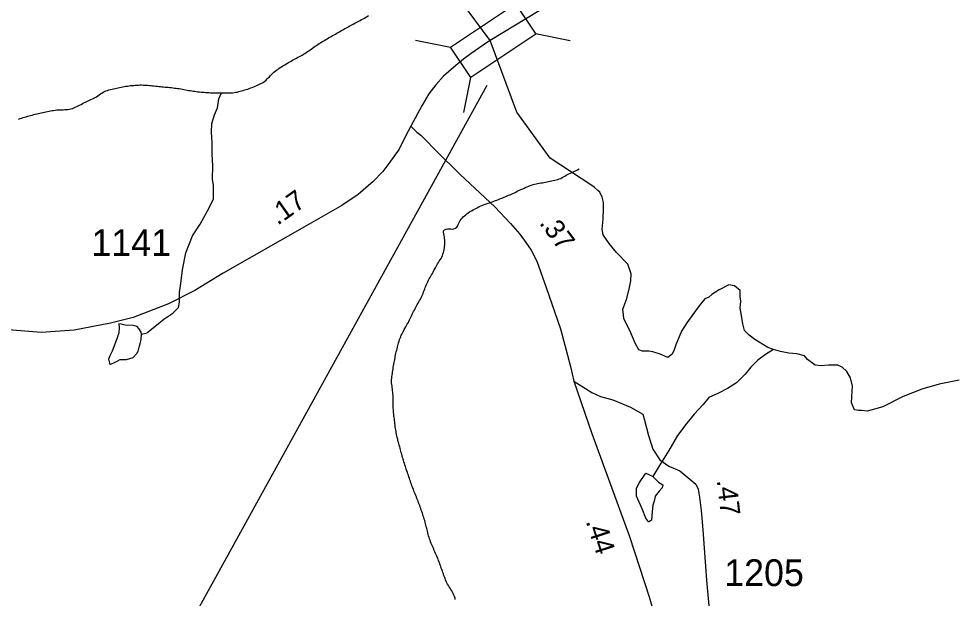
# Model space of a CAD drawing. Extents: x 1950930 to 2061844, y 904556 to 1017002.
# Drawn here: x 1996439 to 2002388, y 935305 to 938988 of the extents above; entities that cross this region are included whole.
import ezdxf

# ---------------------------------------------------------------- set-up
doc = ezdxf.new("R2010")
doc.units = 0
for name, color, linetype in [('Exist Hydrographic Creek Single Shore', 7, 'Continuous'), ('Exist Hydrographic Misc Water Feature', 7, 'Continuous'), ('Exist Road Primary US Structure Standard Bridge CELL', 7, 'Continuous'), ('Exist Road Secondary Structure Standard Bridge CELL', 7, 'Continuous'), ('Exist Road Secondary Structure Standard Bridge Number Label', 7, 'Continuous'), ('Exist Road Secondary Type 51 Attributed', 7, 'Continuous'), ('Exist Road Secondary Type 51 Number Label', 7, 'Continuous')]:
    doc.layers.add(name, color=color, linetype=linetype)

msp = doc.modelspace()

# ---------------------------------------------------------------- linework, layer by layer
at = {"layer": 'Exist Hydrographic Creek Single Shore'}
for points in [[(2000079.1, 937928.9), (1999814, 938102), (1999602, 938394.6), (1999434.4, 938849.1), (1999244, 939104.3), (1999193.9, 939144.7)], [(1997726.7, 938516.3), (1997736.5, 938516.9), (1997747, 938517.3), (1997756.6, 938517.4), (1997766.9, 938517.1), (1997777.1, 938517.6), (1997787, 938518.2), (1997796.8, 938518.3), (1997806.9, 938519.6), (1997816.7, 938520.9), (1997826.3, 938522.4), (1997836.2, 938524.9), (1997845.4, 938527.5), (1997855.3, 938530), (1997865.1, 938533), (1997874.7, 938535.3), (1997884.4, 938538.7), (1997894.2, 938541.6), (1997903.6, 938544.7), (1997913.1, 938548.5), (1997922.5, 938551.5), (1997932.2, 938555.4), (1997941.2, 938559.3), (1997950.8, 938563.5), (1997959.6, 938567.4), (1997968.9, 938571.3), (1997977.7, 938576), (1997986.5, 938580.8), (1997994.5, 938585.2), (1998002.3, 938591.8), (1998009.9, 938598.3), (1998017.5, 938605.3), (1998024.2, 938612.8), (1998031.2, 938619.9), (1998038, 938627.3), (1998044.7, 938634.4), (1998052.3, 938641.8), (1998059.7, 938648), (1998067.7, 938654.5), (1998075.5, 938661), (1998084.1, 938666.2), (1998091.7, 938671.9), (1998100.3, 938677.5), (1998108.5, 938683.1), (1998117.1, 938688.8), (1998125.5, 938693.6), (1998134.5, 938699.1), (1998142.5, 938703.5), (1998151.6, 938709.1), (1998160, 938714.3), (1998168.6, 938719.5), (1998177.4, 938724.2), (1998185.8, 938729.1), (1998195.2, 938733.7), (1998203.6, 938738.5), (1998212.5, 938743.3), (1998221.3, 938748), (1998230.1, 938752.7), (1998239.1, 938757.5), (1998247.5, 938763.1), (1998256.1, 938767.9), (1998264.7, 938773.4), (1998272.7, 938779.1), (1998280.9, 938784.4), (1998289.6, 938790), (1998297.3, 938795.7), (1998305.8, 938801.3), (1998314, 938807), (1998322.4, 938813.4), (1998330.4, 938818.7), (1998338.6, 938824.3), (1998347.2, 938829.9), (1998355.4, 938835.6), (1998363.8, 938840.4), (1998372.4, 938846), (1998380.8, 938850.8), (1998389.8, 938856.3), (1998398.2, 938860.7), (1998406.6, 938865.9), (1998415.3, 938871.2), (1998424.1, 938875.9), (1998432.9, 938880.6), (1998441.5, 938886.2), (1998449.9, 938891), (1998458.7, 938895.8), (1998467.7, 938900.5), (1998476.6, 938905.2), (1998485.2, 938910.8), (1998494, 938915.5), (1998502.4, 938920.4), (1998511.2, 938925.1), (1998520.2, 938929.9), (1998529.1, 938934.6), (1998537.7, 938940.2), (1998546.5, 938945), (1998554.9, 938949.7), (1998563.7, 938954.5), (1998572.7, 938959.2), (1998581.6, 938963.9), (1998590.4, 938968.7)], [(1996816.5, 938434.3), (1996825.7, 938439), (1996834.7, 938443.7), (1996843.5, 938448.5), (1996852.8, 938453.2), (1996862, 938457.1), (1996870.8, 938461.8), (1996879.4, 938465.8), (1996888.6, 938469.7), (1996897.9, 938474.3), (1996907.1, 938478.2), (1996915.9, 938482.9), (1996924.7, 938487.7), (1996933.8, 938492.4), (1996941.7, 938498.1), (1996950.6, 938504.4), (1996958.4, 938510.2), (1996967, 938515.8), (1996975.4, 938520.9), (1996983.8, 938525.7), (1996993, 938529.6), (1997002, 938532.7), (1997011.9, 938535.4), (1997021.7, 938538.3), (1997031.4, 938540.5), (1997040.6, 938542.8), (1997050.8, 938544.8), (1997060.5, 938547.4), (1997070.3, 938549.5), (1997080, 938551.8), (1997090, 938553.8), (1997099.6, 938555.7), (1997109.7, 938557), (1997119.9, 938559.1), (1997129.8, 938560.4), (1997139.8, 938562.1), (1997149.3, 938562.8), (1997159.7, 938564), (1997169.6, 938564.5), (1997179.2, 938566.2), (1997189.5, 938566.8), (1997199.3, 938566.4), (1997209.1, 938567.1), (1997219.4, 938567.1), (1997229, 938566.9), (1997239.3, 938566.5), (1997249.3, 938565.4), (1997259, 938565.1), (1997269, 938564.4), (1997279.5, 938563.3), (1997289.5, 938562.1), (1997299.2, 938561), (1997309.2, 938560.3), (1997319.3, 938559.3), (1997329.1, 938558.1), (1997339.1, 938557), (1997348.8, 938556), (1997358.8, 938555.3), (1997368.9, 938554.1), (1997379.1, 938553.7), (1997389, 938552.7), (1997399.2, 938552), (1997408.7, 938550.9), (1997419.1, 938548.9), (1997428.5, 938547.9), (1997438.6, 938546.8), (1997448.4, 938544.8), (1997458.5, 938544.1), (1997468.5, 938542.3), (1997478.4, 938540.3), (1997487.8, 938538.5), (1997497.6, 938536.5), (1997507.9, 938534.6), (1997517.5, 938532.7), (1997527.4, 938531.2), (1997537.4, 938530.2), (1997546.9, 938528.3), (1997557.3, 938527.1), (1997566.7, 938525.2), (1997576.8, 938524.5), (1997586.8, 938523.4), (1997596.9, 938522.3), (1997606.5, 938522.1), (1997616.6, 938520.9), (1997626.6, 938520.2), (1997636.9, 938519.9), (1997646.9, 938518.8), (1997656.4, 938517.7), (1997666.6, 938517.3), (1997676.9, 938517.4), (1997686.5, 938517.2), (1997696.8, 938516.8), (1997706.4, 938516.6), (1997726.7, 938516.3)], [(1996437.9, 938350.2), (1996447.4, 938354), (1996456.8, 938357.1), (1996466.6, 938360.1), (1996476.5, 938362.2), (1996485.9, 938365.7), (1996495.4, 938368.7), (1996505, 938370.8), (1996514.4, 938373.9), (1996524.3, 938376.1), (1996534.1, 938379), (1996543.7, 938381.6), (1996553.6, 938383.8), (1996563.2, 938386), (1996572.9, 938388.2), (1996582.3, 938390.8), (1996592.3, 938392.9), (1996602.2, 938395.1), (1996611.8, 938397.3), (1996621.9, 938398.9), (1996631.7, 938401.2), (1996641.3, 938403.3), (1996651.4, 938404.7), (1996660.8, 938406), (1996670.9, 938407.7), (1996681.3, 938408.2), (1996691.2, 938408.8), (1996701, 938409.7), (1996711.3, 938409.4), (1996721.5, 938409.8), (1996731.8, 938410.3), (1996741.2, 938411.2), (1996751.1, 938411.8), (1996761.1, 938413.2), (1996770.3, 938415.3), (1996779.8, 938418.4), (1996789.2, 938421.5), (1996798.4, 938425.7), (1996807.9, 938430.4), (1996816.5, 938434.3)], [(2001233.7, 936885.8), (2001197.8, 936897.7), (2001113.6, 936949.6), (2001077.7, 936977.6), (2001049.8, 937005.7), (2001037.5, 937049.6), (2001029.4, 937101.6), (2001021.6, 937149.7), (2001025.4, 937193.6), (2001021.4, 937221.6), (2001021.6, 937261.6), (2000985.4, 937289.6), (2000949.5, 937297.6), (2000887.4, 937265.4), (2000841.5, 937235.5), (2000821.5, 937219.5), (2000797.6, 937207.5), (2000761.6, 937163.3), (2000721.4, 937107.4), (2000681.6, 937055.3), (2000649.7, 937003.5), (2000613.7, 936915.3), (2000601.6, 936883.4), (2000589.8, 936855.4), (2000561.9, 936835.3), (2000513.7, 936855.3), (2000465.8, 936871.1), (2000441.6, 936875.2), (2000401.6, 936875.4), (2000377.8, 936883.1), (2000353.7, 936927.2), (2000319.6, 937007), (2000295.7, 937055.1), (2000283.4, 937083.3), (2000279.7, 937107.3), (2000275.5, 937143.2), (2000299.4, 937203.1), (2000315.5, 937269.3), (2000327.5, 937323.2), (2000329.3, 937367.2), (2000307.3, 937427.4), (2000235.3, 937503), (2000189.3, 937559.1), (2000151.4, 937615), (2000145.2, 937651.2), (2000151.1, 937715.1), (2000153.1, 937781), (2000153, 937821.1), (2000145.1, 937853.1), (2000129, 937885.2), (2000117.1, 937897), (2000093, 937917.2), (2000079.1, 937928.9)], [(2002412, 936690.4), (2002285.8, 936666.4), (2002175.9, 936634.3), (2002055.8, 936586.2), (2001928.1, 936522.2), (2001874, 936506.3), (2001828.1, 936494.1), (2001792.1, 936498.1), (2001772.1, 936498.2), (2001747.9, 936502), (2001728.1, 936546), (2001729.9, 936586), (2001733.9, 936653.9), (2001721.9, 936706), (2001697.8, 936745.9), (2001669.8, 936774), (2001641.8, 936786.1), (2001581.8, 936786), (2001533.8, 936782.1), (2001497.7, 936785.8), (2001449.6, 936821.9), (2001429.8, 936845.9), (2001381.8, 936857.8), (2001329.7, 936861.8), (2001277.7, 936873.7), (2001233.7, 936885.8)]]:
    msp.add_lwpolyline(points, dxfattribs=at)
at = {"layer": 'Exist Hydrographic Misc Water Feature'}
for points in [[(1998590.4, 938968.7), (1998598.8, 938973.1), (1998607.6, 938977.9), (1998616.6, 938983), (1998625.8, 938987.6), (1998634.5, 938991.2), (1998643.1, 938997.2), (1998651.5, 939001.6), (1998661.5, 939008.2)], [(1997219.2, 936982.6), (1997253.8, 936992), (1997259.4, 936996.9), (1997273.9, 937009.7), (1997325.6, 937050.1), (1997361.3, 937078.4), (1997417.5, 937116.5), (1997452.7, 937152.5), (1997460.7, 937187.1), (1997459.9, 937249.2), (1997467.5, 937304.9), (1997478.8, 937393.2), (1997500.3, 937501.2), (1997543.6, 937607.9), (1997590.5, 937681.5), (1997638.1, 937768), (1997675.6, 937841.9), (1997676.9, 937928.1), (1997670.3, 937968.5), (1997671.9, 938052.3), (1997667, 938127.6), (1997666.6, 938198.4), (1997664.1, 938268.1), (1997666, 938322.2), (1997681.6, 938377.5), (1997700.9, 938422.5), (1997710.7, 938478.2), (1997726.7, 938516.3)], [(1999337.4, 937779.7), (1999345.8, 937784.5), (1999355, 937789.5), (1999363.8, 937793.9), (1999373.1, 937798.1), (1999382.3, 937802), (1999391.5, 937805.9), (1999400.9, 937809), (1999410.2, 937812), (1999419.6, 937815), (1999429, 937818), (1999438.7, 937821.9), (1999448.5, 937825.3), (1999457.5, 937828.4), (1999467.2, 937832.2), (1999476.4, 937836.1), (1999485.8, 937839), (1999494.9, 937842.9), (1999504.5, 937847.1), (1999513.5, 937850.3), (1999522.7, 937854.2), (1999532.2, 937858), (1999541.4, 937861.9), (1999550.6, 937865.8), (1999559.6, 937869.7), (1999568.9, 937873.5), (1999577.7, 937878.3), (1999586.9, 937882.2), (1999595.7, 937886.9), (1999604.6, 937891.6), (1999613.4, 937896.3), (1999623, 937900.2), (1999631.6, 937904.1), (1999640.8, 937908), (1999650.1, 937911.9), (1999659.3, 937916.9), (1999668.5, 937920.4), (1999678, 937923.9), (1999687, 937927.8), (1999696.4, 937930.8), (1999706.1, 937934.7), (1999715.3, 937936.8), (1999724.7, 937939.9), (1999734.8, 937941.7), (1999745, 937943.7), (1999754.4, 937945.1), (1999764.9, 937945.5), (1999774.5, 937947.4), (1999784.2, 937949.5), (1999794.6, 937950.8), (1999804.3, 937953), (1999813.9, 937954.8), (1999823.8, 937956.9), (1999833.8, 937959.1), (1999843.4, 937961.2), (1999853.3, 937963.4), (1999862.7, 937966.9), (1999871.7, 937969.9), (1999881.4, 937973.7), (1999890.2, 937978.5), (1999898.8, 937984.1), (1999907, 937988.5), (1999916.2, 937994.5), (1999924.8, 937998.3), (1999933.7, 938003.2), (1999943.3, 938007), (1999952.5, 938010.9), (1999961.6, 938014.8), (1999970.6, 938019.5), (1999979.4, 938024.2), (1999988.2, 938028.9), (1999997.8, 938033.5)], [(1998869, 936976.6), (1998873.5, 936985.3), (1998878.1, 936994.3), (1998882.6, 937003.3), (1998887.3, 937012.4), (1998892, 937020.1), (1998896.9, 937029.2), (1998901.8, 937038.2), (1998906.8, 937047.2), (1998911.7, 937056.1), (1998916, 937064.8), (1998920.5, 937073.9), (1998925, 937083), (1998929.5, 937091.6), (1998934, 937100.6), (1998938.3, 937109.8), (1998942.4, 937118.5), (1998947.4, 937127.5), (1998951.9, 937136.5), (1998956.2, 937145.2), (1998960.7, 937154.3), (1998965.6, 937163.3), (1998970.3, 937171.5), (1998975.7, 937180.4), (1998981, 937188.9), (1998985.5, 937197.9), (1998990.6, 937206.1), (1998995.1, 937215.2), (1998999, 937223.9), (1999003.3, 937233.8), (1999006.8, 937242.6), (1999010.7, 937252.6), (1999014.2, 937261.4), (1999017.9, 937270.5), (1999021.2, 937280.2), (1999025.3, 937288.9), (1999029, 937298.9), (1999033.5, 937307.9), (1999037.6, 937316.7), (1999042.5, 937325.7), (1999046.8, 937334.7), (1999051.7, 937343.3), (1999056.5, 937351.5), (1999061.4, 937360.5), (1999066.3, 937369.6), (1999071.2, 937378.5), (1999075.7, 937387.6), (1999080.4, 937395.4), (1999085.4, 937404.4), (1999089.7, 937413.4), (1999094.6, 937422.5), (1999099.5, 937431.1), (1999104.6, 937439.2), (1999110, 937448.1), (1999115.9, 937456.1), (1999121.2, 937465.1), (1999126.6, 937473.2), (1999130.1, 937482.4), (1999133.3, 937492.1), (1999136.4, 937501.7), (1999138.9, 937511.6), (1999140.9, 937521.4), (1999143, 937531.1), (1999144.2, 937541.2), (1999145.4, 937550.7), (1999146.3, 937560.8), (1999146.1, 937570.5), (1999145.2, 937581.2), (1999144, 937591.1), (1999142.8, 937601.1), (1999141.8, 937610.9), (1999138.9, 937621.5), (1999136.8, 937632.3), (1999136.8, 937640.4), (1999143.2, 937646.8), (1999153.2, 937651.4), (1999163.3, 937653.9), (1999173.5, 937653.6), (1999183.6, 937652.4), (1999194, 937651.7), (1999203.5, 937652.2), (1999213.1, 937656.1), (1999221.3, 937662.6), (1999226.8, 937669.9), (1999230.5, 937679.4), (1999233.4, 937689.5), (1999237.9, 937698.2), (1999243.5, 937706.3), (1999249.6, 937714.7), (1999256.4, 937721.7), (1999262.9, 937728.8), (1999270.5, 937736.2), (1999277.9, 937742.4), (1999285.9, 937748.9), (1999293.7, 937755.5), (1999302.3, 937760.2), (1999310.7, 937765.4), (1999319.5, 937770.1), (1999327.9, 937774.9), (1999337.4, 937779.7)], [(1997219.2, 936982.6), (1997216.3, 936996.1), (1997202.2, 937018.5), (1997190.5, 937031.6), (1997166.3, 937037.8), (1997116, 937041.4), (1997090.2, 937046.9), (1997073.8, 937049), (1997076.3, 937025.1), (1997074.4, 936991.2), (1997062.9, 936954.8), (1997031.4, 936874.9), (1997017.6, 936846.5), (1997009.8, 936824.5), (1997018.2, 936790.8), (1997028.1, 936794.6), (1997048.2, 936802.5), (1997064.2, 936812.6), (1997083.9, 936823), (1997124, 936821.4), (1997165.9, 936835.3), (1997189.5, 936860.1), (1997197.7, 936875.6), (1997203.2, 936901.8), (1997210.8, 936922.2), (1997216.7, 936952.6), (1997219.2, 936982.6)], [(1998939.8, 936010.9), (1998936.7, 936020.3), (1998933.6, 936030.1), (1998930.5, 936039.1), (1998927.1, 936048.9), (1998923.8, 936057.9), (1998920.3, 936067.1), (1998917.2, 936077.2), (1998914.1, 936086.2), (1998910.7, 936096.1), (1998907.4, 936105.1), (1998904.5, 936115.3), (1998900.8, 936124.4), (1998897.7, 936134.1), (1998894.7, 936143.1), (1998891.6, 936153), (1998888.5, 936162.3), (1998885.4, 936172.2), (1998882.8, 936181.1), (1998879.7, 936190.9), (1998877, 936200.2), (1998874, 936210), (1998871.3, 936220.1), (1998868.8, 936229.9), (1998866, 936238.8), (1998863.5, 936248.9), (1998861.2, 936258.6), (1998858.6, 936267.9), (1998856.3, 936277.7), (1998853.2, 936287.4), (1998850.8, 936297.5), (1998847.9, 936306.5), (1998845.9, 936316.6), (1998843.6, 936326.3), (1998840.9, 936336.4), (1998838.7, 936345.6), (1998837, 936355.3), (1998835.6, 936365.2), (1998834, 936375.2), (1998832.1, 936384.8), (1998830.7, 936394.7), (1998829.9, 936404.6), (1998828.6, 936415.3), (1998827.4, 936425.3), (1998826, 936435.2), (1998825.2, 936444.8), (1998823.7, 936454.6), (1998822.5, 936464.6), (1998821.1, 936474.5), (1998820.2, 936484.5), (1998819.4, 936494.3), (1998818.4, 936504.1), (1998818, 936514), (1998817.6, 936524.6), (1998818, 936534.3), (1998818, 936544.4), (1998817.8, 936554.2), (1998817.8, 936563.9), (1998817.8, 936574.5), (1998817.4, 936584.7), (1998816.3, 936594.2), (1998815.9, 936604.4), (1998815.1, 936614.2), (1998813.7, 936623.8), (1998812.8, 936634), (1998811.4, 936643.7), (1998810.6, 936653.5), (1998808.5, 936664.4), (1998807.3, 936674.3), (1998806.3, 936684.2), (1998807.1, 936693.8), (1998808.3, 936703.8), (1998809.2, 936713.4), (1998810.4, 936723.3), (1998812, 936733.3), (1998813.1, 936742.8), (1998815.3, 936753.5), (1998816.5, 936763.4), (1998818.2, 936773.3), (1998820.2, 936783.1), (1998821.9, 936793.1), (1998823.5, 936802.5), (1998825.6, 936812.3), (1998826.8, 936822.3), (1998829.3, 936832.1), (1998830.9, 936842), (1998832.9, 936851.8), (1998834.6, 936861.7), (1998837, 936871.1), (1998839.5, 936881.2), (1998842.2, 936891), (1998844.6, 936900.8), (1998846.7, 936910.7), (1998849.6, 936920.3), (1998851.8, 936929.3), (1998854.7, 936939.1), (1998858, 936948.7), (1998861.2, 936957.9), (1998864.9, 936967.5), (1998869, 936976.6)], [(2001233.7, 936885.8), (2001181.8, 936853.7), (2001133.8, 936817.6), (2001089.9, 936773.5), (2001053.9, 936729.6), (2000997.9, 936673.7), (2000941.7, 936637.5), (2000883.7, 936609.4), (2000821.8, 936581.5), (2000786.1, 936537.3), (2000730, 936475.4), (2000681.9, 936417.4), (2000622.2, 936339.2), (2000568, 936243.2), (2000504.2, 936143.1), (2000466.1, 936079.2)], [(2000466.1, 936079.2), (2000502.2, 936043.3), (2000530.3, 936025.4), (2000526.3, 936007.1), (2000506.2, 935985.2), (2000482.2, 935953.2), (2000482.2, 935951.2), (2000474.4, 935921.2), (2000466.3, 935897.1), (2000462.2, 935857.1), (2000458.4, 935801.1), (2000438.5, 935789), (2000434.4, 935797.3), (2000422.3, 935813.3), (2000398.2, 935873.2), (2000362.1, 935953), (2000362.4, 935981.3), (2000362.2, 936005.2), (2000382.3, 936041.2), (2000422.3, 936099.1), (2000446, 936089.1), (2000466.1, 936079.2)], [(1999184.2, 935360.9), (1999178.9, 935369.5), (1999173.3, 935377.6), (1999168, 935386.1), (1999162.9, 935394.2), (1999158.6, 935403.3), (1999154.5, 935412.4), (1999150.6, 935421.7), (1999147.1, 935431.5), (1999143.4, 935440.5), (1999139.9, 935449.7), (1999136.4, 935459.9), (1999132.9, 935468.9), (1999129.7, 935478), (1999126.4, 935487.8), (1999123.1, 935496.8), (1999119.6, 935506.7), (1999116.5, 935515.7), (1999113, 935525.1), (1999109.6, 935535), (1999105.9, 935544.1), (1999102.8, 935553.1), (1999098.9, 935562.9), (1999094.8, 935572.2), (1999091.3, 935581.2), (1999086.8, 935590.4), (1999082.9, 935599.5), (1999078.4, 935608.7), (1999074.5, 935617.8), (1999070.4, 935627), (1999066.3, 935635.7), (1999062.4, 935644.9), (1999058.3, 935654), (1999055, 935664.2), (1999051.3, 935673.3), (1999048.7, 935682.3), (1999045.6, 935692), (1999042.5, 935701.9), (1999039.8, 935711.2), (1999037.2, 935720.9), (1999035.1, 935731), (1999032.3, 935739.9), (1999030.2, 935750), (1999027.5, 935759.7), (1999025.3, 935769.7), (1999022.8, 935779.5), (1999020, 935788.5), (1999017.9, 935798.6), (1999015.2, 935808.3), (1999011.8, 935817.7), (1999008.7, 935827.6), (1999005.8, 935836.5), (1999002.5, 935846.3), (1998998.8, 935855.4), (1998995.8, 935865.2), (1998992.3, 935874.6), (1998989.2, 935883.6), (1998985.7, 935893.5), (1998982, 935902.6), (1998978.5, 935911.6), (1998975, 935921.5), (1998971.4, 935930.6), (1998967.9, 935939.6), (1998964.4, 935949.2), (1998960.5, 935959), (1998956.8, 935968.1), (1998952.9, 935977.3), (1998949.2, 935986.3), (1998945.7, 935996.1), (1998939.8, 936010.9)], [(1999211.7, 935296.3), (1999210.2, 935306.2), (1999207.2, 935315.6), (1999203.3, 935325.5), (1999198.8, 935334.3), (1999194, 935343.5), (1999189.5, 935351.9), (1999184.2, 935360.9)]]:
    msp.add_lwpolyline(points, dxfattribs=at)
at = {"layer": 'Exist Road Secondary Structure Standard Bridge CELL'}
for p, q in [((1999720.5, 938893.7), (1999942.5, 938849.4)), ((1998959.9, 938852), (1999181.9, 938807.7)), ((1999266.1, 938393.1), (1999310.4, 938615))]:
    msp.add_line(p, q, dxfattribs=at)
msp.add_lwpolyline([(1999181.9, 938807.7), (1999594.2, 939082.8), (1999722.8, 938890.2), (1999310.4, 938615)], close=True, dxfattribs=at)
at = {"layer": 'Exist Road Secondary Structure Standard Bridge Number Label'}
msp.add_line((1999411.6, 938564.8), (1997182.9, 934520.1), dxfattribs=at)
at = {"layer": 'Exist Road Secondary Type 51 Attributed'}
for points in [[(2002393.9, 941261.3), (2002177.9, 941021.3), (2002000, 940829.2), (2001912, 940733.2), (2001830.2, 940665), (2001732.7, 940583.2), (2001621.3, 940500.4), (2001440.1, 940377.6), (2001303.2, 940287.3), (2001203.1, 940211.3), (2001079.8, 940125.5), (2000971.5, 940051.7), (2000810.5, 939937.3), (2000658.5, 939827.1), (2000537.9, 939730.3), (2000397.6, 939602.3), (2000245.3, 939465.1), (2000100.2, 939335.4), (1999909, 939169.2), (1999837.3, 939104.3), (1999744, 939038.3), (1999434.4, 938849.1)], [(1999434.4, 938849.1), (1999417.1, 938839.1), (1999311.8, 938766.8), (1999263.7, 938732.2), (1999215.6, 938691.5), (1999137.3, 938622.9), (1999087.2, 938567.1), (1999042.8, 938510.2), (1998999.6, 938435), (1998928.4, 938306.4)], [(1998928.4, 938306.4), (1998895.9, 938242.1), (1998854.5, 938158.6), (1998789.8, 938068.2), (1998751.5, 938017.3), (1998690, 937954.7), (1998595.5, 937871.6), (1998491.9, 937802.2), (1998283.6, 937683.5), (1997738.3, 937371.1), (1997557.8, 937261.2), (1997389.3, 937175.4), (1997165.2, 937089.6), (1997022.3, 937053.4), (1996791.3, 937008.3), (1996581.4, 936995), (1996085.5, 937034.1)], [(1998928.4, 938306.4), (1998966.6, 938267.7), (1998992.2, 938248.1), (1999016.2, 938225.6), (1999090, 938148.8), (1999241.9, 937998.2), (1999462.3, 937792.7), (1999561.6, 937687.3), (1999621.7, 937618), (1999660.1, 937566.1), (1999694.7, 937516.4), (1999729.3, 937447.2), (1999788, 937280), (1999880.5, 937017.3), (1999944.4, 936778.7), (1999964.9, 936684.6)], [(1999964.9, 936684.6), (2000078.8, 936352.6), (2000319.1, 935697.8), (2000443.4, 935313.9), (2000479.3, 935185.9), (2000539.5, 935075.9), (2000583.6, 935003.9), (2000663.6, 934900.1), (2000743.6, 934812), (2000947.7, 934658.1)], [(1999964.9, 936684.6), (2000078.7, 936612.5), (2000134.1, 936586.6), (2000212.8, 936566.2), (2000324.5, 936519.9), (2000402.6, 936473.9), (2000414.6, 936436), (2000438.6, 936339.9), (2000466.8, 936251.9), (2000510.8, 936183.9), (2000568.8, 936143.9), (2000638.3, 936115.7)], [(2000638.3, 936115.7), (2000738.8, 936030.2), (2000755, 935998.1), (2000763, 935948.1), (2000773, 935862), (2000783.1, 935740.2), (2000807.2, 935420.2), (2000839.4, 935072.1), (2000873.5, 934920.1), (2000899.6, 934820.2), (2000947.7, 934658.1)]]:
    msp.add_lwpolyline(points, dxfattribs=at)

# ---------------------------------------------------------------- texts
at = {"layer": 'Exist Road Primary US Structure Standard Bridge CELL'}
for s, rotation, p in [('.17', 35.45679, (1998083.2, 937671.6)), ('.37', 306.44559, (1999741.8, 937689.4)), ('.47', 276.6453, (2000872.4, 936054.6)), ('.44', 287.94037, (2000039.7, 935793.9))]:
    msp.add_text(s, height=125, rotation=rotation, dxfattribs=at).set_placement(p)
at = {"layer": 'Exist Road Secondary Type 51 Number Label'}
for s, p in [('1141', (1996900.5, 937480.4)), ('1205', (2000920, 935382.4))]:
    msp.add_text(s, height=170, dxfattribs=at).set_placement(p)

doc.saveas('drawing.dxf')
